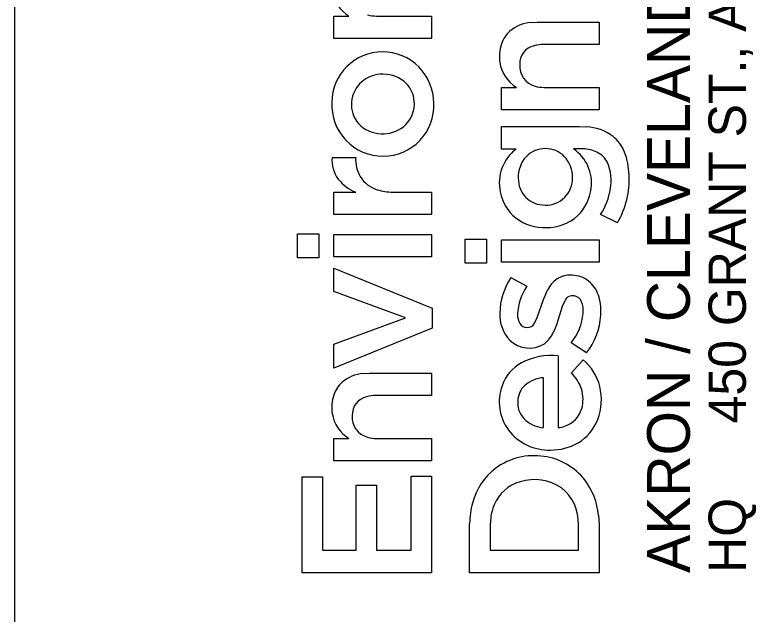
# Model space of a CAD drawing. Extents: x 0 to 54.8, y 0 to 22.
# Drawn here: x 32 to 32.989, y 2.583 to 3.382 of the extents above; entities that cross this region are included whole.
import ezdxf

# ---------------------------------------------------------------- set-up
doc = ezdxf.new("R2010")
doc.units = 0
doc.layers.add('GM_X_Minor_Lake', color=7, linetype='Continuous')
doc.layers.add('GM_X_Township', color=7, linetype='Continuous')

msp = doc.modelspace()

# ---------------------------------------------------------------- linework, layer by layer
at = {"layer": 'GM_X_Minor_Lake'}
for p, q in [((32.42542, 3.38066), (32.44552, 3.38071)), ((32.42542, 3.35086), (32.42542, 3.38066)), ((32.48222, 3.38071), (32.55569, 3.38071)), ((32.55569, 3.38071), (32.55571, 3.35096)), ((32.68784, 3.3722), (32.69634, 3.37266)), ((32.69634, 3.37266), (32.77916, 3.37266)), ((32.77916, 3.37266), (32.77917, 3.34287)), ((32.55571, 3.35096), (32.42542, 3.35086)), ((32.77917, 3.34287), (32.70485, 3.3428)), ((32.64888, 3.2855), (32.66897, 3.28555)), ((32.64888, 3.25569), (32.64888, 3.2855)), ((32.70568, 3.28555), (32.77915, 3.28555)), ((32.77915, 3.28555), (32.77917, 3.25579)), ((32.77917, 3.25579), (32.64888, 3.25569)), ((32.6489, 3.20336), (32.64889, 3.23322)), ((32.64889, 3.23322), (32.75236, 3.23322)), ((32.75236, 3.23322), (32.76191, 3.23285)), ((32.66836, 3.20336), (32.6489, 3.20336)), ((32.75763, 3.20356), (32.74487, 3.20361)), ((32.42299, 3.19193), (32.45454, 3.19193)), ((32.42542, 3.14577), (32.45473, 3.14579)), ((32.42542, 3.11593), (32.42542, 3.14577)), ((32.50413, 3.14581), (32.55571, 3.14573)), ((32.55571, 3.14573), (32.55565, 3.11593)), ((32.55565, 3.11593), (32.42542, 3.11593)), ((32.8036, 3.10491), (32.7812, 3.11598)), ((32.37705, 3.05818), (32.37705, 3.09026)), ((32.37705, 3.09026), (32.40543, 3.09026)), ((32.40543, 3.09026), (32.40543, 3.05818)), ((32.42542, 3.05942), (32.42542, 3.08928)), ((32.42542, 3.08928), (32.55571, 3.08928)), ((32.55571, 3.08928), (32.55571, 3.05942)), ((32.60051, 3.05111), (32.60051, 3.08319)), ((32.60051, 3.08319), (32.62889, 3.08319)), ((32.62889, 3.08319), (32.62889, 3.05111)), ((32.64888, 3.05234), (32.64888, 3.0822)), ((32.64888, 3.0822), (32.77917, 3.0822)), ((32.77917, 3.0822), (32.77917, 3.05234)), ((32.40543, 3.05818), (32.37705, 3.05818)), ((32.55571, 3.05942), (32.42542, 3.05942)), ((32.62889, 3.05111), (32.60051, 3.05111)), ((32.77917, 3.05234), (32.64888, 3.05234)), ((32.42542, 3.01327), (32.42542, 3.0446)), ((32.42542, 3.0446), (32.5567, 2.9913)), ((32.66151, 3.03207), (32.68268, 3.02025)), ((32.70483, 3.00258), (32.71036, 3.01526)), ((32.52117, 2.97798), (32.42542, 3.01327)), ((32.69675, 2.97868), (32.70483, 3.00258)), ((32.73342, 3.00101), (32.72985, 2.9933)), ((32.5567, 2.9913), (32.5567, 2.96441)), ((32.72985, 2.9933), (32.72213, 2.96882)), ((32.42542, 2.94294), (32.52117, 2.97798)), ((32.69299, 2.97117), (32.69675, 2.97868)), ((32.72213, 2.96882), (32.71822, 2.95921)), ((32.5567, 2.96441), (32.42542, 2.91086)), ((32.42542, 2.91086), (32.42542, 2.94294)), ((32.76214, 2.93141), (32.74198, 2.94469)), ((32.72453, 2.92747), (32.72463, 2.83195)), ((32.74228, 2.90465), (32.75768, 2.922)), ((32.46439, 2.90397), (32.47289, 2.90443)), ((32.47289, 2.90443), (32.55571, 2.90443)), ((32.55571, 2.90443), (32.55571, 2.87465)), ((32.70489, 2.83182), (32.70489, 2.89834)), ((32.55571, 2.87465), (32.4814, 2.87457)), ((32.70361, 2.83165), (32.70489, 2.83182)), ((32.42542, 2.81728), (32.44552, 2.81733)), ((32.42542, 2.78747), (32.42542, 2.81728)), ((32.48222, 2.81733), (32.55569, 2.81733)), ((32.55569, 2.81733), (32.55571, 2.78756)), ((32.55571, 2.78756), (32.42542, 2.78747)), ((32.38298, 2.63791), (32.38298, 2.76598)), ((32.38298, 2.76598), (32.41012, 2.76598)), ((32.41012, 2.76598), (32.41012, 2.66827)), ((32.52857, 2.66827), (32.52857, 2.76722)), ((32.52857, 2.76722), (32.55571, 2.76722)), ((32.55571, 2.76722), (32.55571, 2.63791)), ((32.45503, 2.66827), (32.45503, 2.75488)), ((32.45503, 2.75488), (32.48218, 2.75488)), ((32.48218, 2.75488), (32.48218, 2.66827)), ((32.63465, 2.71178), (32.63407, 2.7023)), ((32.77847, 2.71497), (32.77917, 2.7021)), ((32.60643, 2.63799), (32.60644, 2.704)), ((32.63407, 2.7023), (32.63407, 2.66838)), ((32.75149, 2.66834), (32.75153, 2.70239)), ((32.77917, 2.7021), (32.77917, 2.638)), ((32.41012, 2.66827), (32.45503, 2.66827)), ((32.48218, 2.66827), (32.52857, 2.66827)), ((32.63407, 2.66838), (32.75149, 2.66834)), ((32.55571, 2.63791), (32.38298, 2.63791)), ((32.77917, 2.638), (32.60643, 2.63799))]:
    msp.add_line(p, q, dxfattribs=at)
for points in [[(32.42542, 3.35086), (32.42542, 3.38066), (32.44552, 3.38071)], [(32.48222, 3.38071), (32.55569, 3.38071), (32.55571, 3.35096), (32.42542, 3.35086)], [(32.68784, 3.3722), (32.69634, 3.37266), (32.77916, 3.37266), (32.77917, 3.34287), (32.70485, 3.3428)], [(32.64888, 3.25569), (32.64888, 3.2855), (32.66897, 3.28555)], [(32.70568, 3.28555), (32.77915, 3.28555), (32.77917, 3.25579), (32.64888, 3.25569)], [(32.66836, 3.20336), (32.6489, 3.20336), (32.64889, 3.23322), (32.75236, 3.23322), (32.76191, 3.23285)], [(32.75763, 3.20356), (32.74487, 3.20361)], [(32.42299, 3.19193), (32.45454, 3.19193)], [(32.50413, 3.14581), (32.55571, 3.14573), (32.55565, 3.11593), (32.42542, 3.11593)], [(32.42542, 3.11593), (32.42542, 3.14577), (32.45473, 3.14579)], [(32.8036, 3.10491), (32.7812, 3.11598)], [(32.66151, 3.03207), (32.68268, 3.02025)], [(32.69299, 2.97117), (32.69675, 2.97868), (32.70483, 3.00258), (32.71036, 3.01526)], [(32.73342, 3.00101), (32.72985, 2.9933), (32.72213, 2.96882), (32.71822, 2.95921)], [(32.76214, 2.93141), (32.74198, 2.94469)], [(32.72453, 2.92747), (32.72463, 2.83195)], [(32.74228, 2.90465), (32.75768, 2.922)], [(32.46439, 2.90397), (32.47289, 2.90443), (32.55571, 2.90443), (32.55571, 2.87465), (32.4814, 2.87457)], [(32.70361, 2.83165), (32.70489, 2.83182), (32.70489, 2.89834)], [(32.42542, 2.78747), (32.42542, 2.81728), (32.44552, 2.81733)], [(32.48222, 2.81733), (32.55569, 2.81733), (32.55571, 2.78756), (32.42542, 2.78747)], [(32.77847, 2.71497), (32.77917, 2.7021), (32.77917, 2.638), (32.60643, 2.63799)], [(32.63465, 2.71178), (32.63407, 2.7023), (32.63407, 2.66838), (32.75149, 2.66834), (32.75153, 2.70239)], [(32.60643, 2.63799), (32.60644, 2.704)]]:
    msp.add_lwpolyline(points, dxfattribs=at)
for points in [[(32.37705, 3.05818), (32.37705, 3.09026), (32.40543, 3.09026), (32.40543, 3.05818)], [(32.42542, 3.05942), (32.42542, 3.08928), (32.55571, 3.08928), (32.55571, 3.05942)], [(32.60051, 3.05111), (32.60051, 3.08319), (32.62889, 3.08319), (32.62889, 3.05111)], [(32.64888, 3.05234), (32.64888, 3.0822), (32.77917, 3.0822), (32.77917, 3.05234)], [(32.42542, 2.91086), (32.42542, 2.94294), (32.52117, 2.97798), (32.42542, 3.01327), (32.42542, 3.0446), (32.5567, 2.9913), (32.5567, 2.96441)], [(32.38298, 2.63791), (32.38298, 2.76598), (32.41012, 2.76598), (32.41012, 2.66827), (32.45503, 2.66827), (32.45503, 2.75488), (32.48218, 2.75488), (32.48218, 2.66827), (32.52857, 2.66827), (32.52857, 2.76722), (32.55571, 2.76722), (32.55571, 2.63791)]]:
    msp.add_lwpolyline(points, close=True, dxfattribs=at)
for centre, radius, start, end in [((32.47027, 3.42141), 0.04763, 188.96462, 238.69865), ((32.47027, 3.42141), 0.04763, 188.96462, 238.69865), ((32.48183, 3.42286), 0.04215, 254.08913, 270.52838), ((32.48183, 3.42286), 0.04215, 254.08913, 270.52838), ((32.69216, 3.32251), 0.04988, 94.97056, 130.22484), ((32.69216, 3.32251), 0.04988, 94.97056, 130.22484), ((32.68694, 3.33085), 0.04016, 132.22383, 161.68229), ((32.68694, 3.33085), 0.04016, 132.22383, 161.68229), ((32.70217, 3.32642), 0.05602, 162.27398, 187.79173), ((32.70217, 3.32642), 0.05602, 162.27398, 187.79173), ((32.70453, 3.29679), 0.04601, 89.60515, 105.33026), ((32.70453, 3.29679), 0.04601, 89.60515, 105.33026), ((32.49014, 3.26543), 0.0674, 89.84756, 179.64047), ((32.49014, 3.26543), 0.0674, 89.84756, 179.64047), ((32.49057, 3.26474), 0.0681, 359.54009, 90.21138), ((32.49057, 3.26474), 0.0681, 359.54009, 90.21138), ((32.69828, 3.31689), 0.02498, 103.68683, 182.21395), ((32.69828, 3.31689), 0.02498, 103.68683, 182.21395), ((32.69372, 3.32624), 0.04763, 188.96462, 238.69865), ((32.69372, 3.32624), 0.04763, 188.96462, 238.69865), ((32.7008, 3.31381), 0.02757, 175.58441, 255.13816), ((32.7008, 3.31381), 0.02757, 175.58441, 255.13816), ((32.48923, 3.26263), 0.0404, 87.04809, 175.57259), ((32.48923, 3.26263), 0.0404, 87.04809, 175.57259), ((32.49204, 3.25999), 0.04299, 45.84264, 90.98008), ((32.49204, 3.25999), 0.04299, 45.84264, 90.98008), ((32.49458, 3.26421), 0.03821, 357.88569, 44.15902), ((32.49458, 3.26421), 0.03821, 357.88569, 44.15902), ((32.70529, 3.32769), 0.04215, 254.08913, 270.52838), ((32.70529, 3.32769), 0.04215, 254.08913, 270.52838), ((32.49083, 3.26209), 0.06819, 176.8344, 270.40384), ((32.49083, 3.26209), 0.06819, 176.8344, 270.40384), ((32.48729, 3.2625), 0.03848, 175.15378, 221.14706), ((32.48729, 3.2625), 0.03848, 175.15378, 221.14706), ((32.49123, 3.26139), 0.06749, 270.06243, 2.37759), ((32.49123, 3.26139), 0.06749, 270.06243, 2.37759), ((32.49446, 3.26318), 0.0383, 308.28936, 359.43468), ((32.49446, 3.26318), 0.0383, 308.28936, 359.43468), ((32.48919, 3.26607), 0.04228, 223.09994, 268.80895), ((32.48919, 3.26607), 0.04228, 223.09994, 268.80895), ((32.49096, 3.2679), 0.04418, 266.56515, 308.06078), ((32.49096, 3.2679), 0.04418, 266.56515, 308.06078), ((32.75907, 3.16789), 0.06503, 53.40344, 87.49062), ((32.75907, 3.16789), 0.06503, 53.40344, 87.49062), ((32.76517, 3.18039), 0.05141, 21.60748, 50.5577), ((32.76517, 3.18039), 0.05141, 21.60748, 50.5577), ((32.70292, 3.15813), 0.05692, 127.37482, 192.22468), ((32.70292, 3.15813), 0.05692, 127.37482, 192.22468), ((32.70693, 3.16927), 0.0346, 88.47302, 136.42562), ((32.70693, 3.16927), 0.0346, 88.47302, 136.42562), ((32.70814, 3.16963), 0.03424, 44.27195, 90.47623), ((32.70814, 3.16963), 0.03424, 44.27195, 90.47623), ((32.71421, 3.15829), 0.05472, 352.1125, 55.92295), ((32.71421, 3.15829), 0.05472, 352.1125, 55.92295), ((32.75666, 3.15725), 0.04633, 65.01687, 88.8011), ((32.75666, 3.15725), 0.04633, 65.01687, 88.8011), ((32.71141, 3.16602), 0.0401, 137.46739, 182.33237), ((32.71141, 3.16602), 0.0401, 137.46739, 182.33237), ((32.70368, 3.166), 0.03996, 358.57141, 43.53765), ((32.70368, 3.166), 0.03996, 358.57141, 43.53765), ((32.7626, 3.17155), 0.03085, 26.26808, 63.80301), ((32.7626, 3.17155), 0.03085, 26.26808, 63.80301), ((32.73069, 3.16714), 0.08835, 1.15143, 21.3627), ((32.73069, 3.16714), 0.08835, 1.15143, 21.3627), ((32.46616, 3.18882), 0.04329, 175.87313, 216.34747), ((32.46616, 3.18882), 0.04329, 175.87313, 216.34747), ((32.50087, 3.18948), 0.04639, 176.9688, 209.60636), ((32.50087, 3.18948), 0.04639, 176.9688, 209.60636), ((32.73565, 3.16154), 0.05953, 349.30734, 23.43071), ((32.73565, 3.16154), 0.05953, 349.30734, 23.43071), ((32.49514, 3.18814), 0.04079, 211.94466, 253.2028), ((32.49514, 3.18814), 0.04079, 211.94466, 253.2028), ((32.70645, 3.1637), 0.03511, 178.88208, 271.08374), ((32.70645, 3.1637), 0.03511, 178.88208, 271.08374), ((32.70818, 3.16404), 0.03546, 268.27882, 1.55016), ((32.70818, 3.16404), 0.03546, 268.27882, 1.55016), ((32.70538, 3.16244), 0.11383, 329.6388, 3.25998), ((32.70538, 3.16244), 0.11383, 329.6388, 3.25998), ((32.47466, 3.19716), 0.05511, 218.09809, 248.7907), ((32.47466, 3.19716), 0.05511, 218.09809, 248.7907), ((32.50465, 3.2165), 0.07069, 252.46555, 269.57296), ((32.50465, 3.2165), 0.07069, 252.46555, 269.57296), ((32.70463, 3.15696), 0.05837, 190.75182, 231.28919), ((32.70463, 3.15696), 0.05837, 190.75182, 231.28919), ((32.70988, 3.15708), 0.05887, 313.74196, 353.8554), ((32.70988, 3.15708), 0.05887, 313.74196, 353.8554), ((32.70738, 3.16334), 0.08771, 327.31495, 351.57478), ((32.70738, 3.16334), 0.08771, 327.31495, 351.57478), ((32.70954, 3.15901), 0.06051, 269.6361, 312.70877), ((32.70954, 3.15901), 0.06051, 269.6361, 312.70877), ((32.70632, 3.16112), 0.06269, 232.46061, 272.59022), ((32.70632, 3.16112), 0.06269, 232.46061, 272.59022), ((32.7406, 3.0026), 0.03263, 80.17192, 122.51969), ((32.7406, 3.0026), 0.03263, 80.17192, 122.51969), ((32.73636, 2.98258), 0.08973, 146.53104, 178.7571), ((32.73636, 2.98258), 0.08973, 146.53104, 178.7571), ((32.74661, 2.99713), 0.04053, 125.51182, 153.41595), ((32.74661, 2.99713), 0.04053, 125.51182, 153.41595), ((32.74278, 2.99824), 0.03667, 47.79344, 84.68918), ((32.74278, 2.99824), 0.03667, 47.79344, 84.68918), ((32.73788, 2.9946), 0.04267, 14.9966, 46.20632), ((32.73788, 2.9946), 0.04267, 14.9966, 46.20632), ((32.74519, 2.9789), 0.07495, 146.51121, 176.91007), ((32.74519, 2.9789), 0.07495, 146.51121, 176.91007), ((32.74384, 2.99631), 0.01143, 76.66094, 155.7053), ((32.74384, 2.99631), 0.01143, 76.66094, 155.7053), ((32.74397, 2.99511), 0.01256, 21.5098, 78.52618), ((32.74397, 2.99511), 0.01256, 21.5098, 78.52618), ((32.71044, 2.98674), 0.07121, 355.83062, 15.39138), ((32.71044, 2.98674), 0.07121, 355.83062, 15.39138), ((32.72592, 2.98766), 0.03209, 354.57264, 22.06805), ((32.72592, 2.98766), 0.03209, 354.57264, 22.06805), ((32.69666, 2.98238), 0.05005, 177.53659, 222.79318), ((32.69666, 2.98238), 0.05005, 177.53659, 222.79318), ((32.6931, 2.98233), 0.02276, 178.47474, 211.08679), ((32.6931, 2.98233), 0.02276, 178.47474, 211.08679), ((32.68248, 2.99149), 0.0757, 321.81101, 354.79685), ((32.68248, 2.99149), 0.0757, 321.81101, 354.79685), ((32.68952, 2.9882), 0.09219, 321.9777, 355.87384), ((32.68952, 2.9882), 0.09219, 321.9777, 355.87384), ((32.68331, 2.9767), 0.01148, 212.23676, 268.37769), ((32.68331, 2.9767), 0.01148, 212.23676, 268.37769), ((32.68342, 2.97589), 0.01067, 267.71603, 333.73375), ((32.68342, 2.97589), 0.01067, 267.71603, 333.73375), ((32.68098, 2.9758), 0.04077, 308.08772, 335.98736), ((32.68098, 2.9758), 0.04077, 308.08772, 335.98736), ((32.68599, 2.97535), 0.0375, 225.98539, 302.47965), ((32.68599, 2.97535), 0.0375, 225.98539, 302.47965), ((32.7152, 2.84414), 0.08384, 83.61499, 118.28755), ((32.7152, 2.84414), 0.08384, 83.61499, 118.28755), ((32.70239, 2.86906), 0.05583, 118.83082, 160.62438), ((32.70239, 2.86906), 0.05583, 118.83082, 160.62438), ((32.71744, 2.87167), 0.06443, 13.53365, 51.36148), ((32.71744, 2.87167), 0.06443, 13.53365, 51.36148), ((32.46871, 2.85428), 0.04988, 94.96958, 130.22249), ((32.46871, 2.85428), 0.04988, 94.96958, 130.22249), ((32.70785, 2.85609), 0.04235, 94.00805, 130.88169), ((32.70785, 2.85609), 0.04235, 94.00805, 130.88169), ((32.70378, 2.86556), 0.05486, 19.03571, 45.44059), ((32.70378, 2.86556), 0.05486, 19.03571, 45.44059), ((32.46348, 2.86263), 0.04015, 132.22192, 161.68183), ((32.46348, 2.86263), 0.04015, 132.22192, 161.68183), ((32.71041, 2.86612), 0.06437, 160.52012, 215.78311), ((32.71041, 2.86612), 0.06437, 160.52012, 215.78311), ((32.70048, 2.86628), 0.02985, 132.98507, 177.179), ((32.70048, 2.86628), 0.02985, 132.98507, 177.179), ((32.70635, 2.86921), 0.07579, 339.3542, 13.37853), ((32.70635, 2.86921), 0.07579, 339.3542, 13.37853), ((32.71069, 2.8697), 0.047, 344.60586, 17.007), ((32.71069, 2.8697), 0.047, 344.60586, 17.007), ((32.47872, 2.85819), 0.05601, 162.27355, 187.79185), ((32.47872, 2.85819), 0.05601, 162.27355, 187.79185), ((32.47482, 2.84867), 0.02498, 103.68646, 182.21874), ((32.47482, 2.84867), 0.02498, 103.68646, 182.21874), ((32.48108, 2.82856), 0.04601, 89.60494, 105.3284), ((32.48108, 2.82856), 0.04601, 89.60494, 105.3284), ((32.7017, 2.86503), 0.03115, 175.00126, 223.28301), ((32.7017, 2.86503), 0.03115, 175.00126, 223.28301), ((32.7224, 2.86715), 0.03504, 288.00773, 343.55078), ((32.7224, 2.86715), 0.03504, 288.00773, 343.55078), ((32.47026, 2.85802), 0.04762, 188.96199, 238.70369), ((32.47026, 2.85802), 0.04762, 188.96199, 238.70369), ((32.47735, 2.84558), 0.02756, 175.58538, 255.14386), ((32.47735, 2.84558), 0.02756, 175.58538, 255.14386), ((32.70891, 2.87363), 0.04231, 225.06188, 262.79738), ((32.70891, 2.87363), 0.04231, 225.06188, 262.79738), ((32.71894, 2.8652), 0.0626, 300.94269, 338.73225), ((32.71894, 2.8652), 0.0626, 300.94269, 338.73225), ((32.71253, 2.87054), 0.06872, 217.74516, 271.65431), ((32.71253, 2.87054), 0.06872, 217.74516, 271.65431), ((32.72474, 2.85216), 0.02021, 269.7003, 294.8711), ((32.72474, 2.85216), 0.02021, 269.7003, 294.8711), ((32.48183, 2.85948), 0.04215, 254.09162, 270.52835), ((32.48183, 2.85948), 0.04215, 254.09162, 270.52835), ((32.71549, 2.87241), 0.07056, 269.20477, 300.33412), ((32.71549, 2.87241), 0.07056, 269.20477, 300.33412), ((32.69229, 2.70792), 0.08641, 81.19402, 125.99844), ((32.69229, 2.70792), 0.08641, 81.19402, 125.99844), ((32.69458, 2.71132), 0.08272, 37.85208, 82.40204), ((32.69458, 2.71132), 0.08272, 37.85208, 82.40204), ((32.69387, 2.70893), 0.08654, 127.23621, 165.14796), ((32.69387, 2.70893), 0.08654, 127.23621, 165.14796), ((32.68893, 2.70782), 0.05398, 106.18808, 157.38609), ((32.68893, 2.70782), 0.05398, 106.18808, 157.38609), ((32.69279, 2.69862), 0.06389, 55.67272, 107.20935), ((32.69279, 2.69862), 0.06389, 55.67272, 107.20935), ((32.68586, 2.70567), 0.09308, 5.73329, 37.30396), ((32.68586, 2.70567), 0.09308, 5.73329, 37.30396), ((32.69291, 2.70499), 0.05867, 357.46616, 52.26647), ((32.69291, 2.70499), 0.05867, 357.46616, 52.26647), ((32.71426, 2.70281), 0.10783, 164.7861, 179.37039), ((32.71426, 2.70281), 0.10783, 164.7861, 179.37039), ((32.69829, 2.70389), 0.06412, 157.35705, 172.92755), ((32.69829, 2.70389), 0.06412, 157.35705, 172.92755)]:
    msp.add_arc(centre, radius, start, end, dxfattribs=at)
at = {"layer": 'GM_X_Township'}
msp.add_line((32, 0.5), (32, 21.5), dxfattribs=at)

# ---------------------------------------------------------------- texts
at = {"layer": 'GM_X_Minor_Lake'}
for s, height, p in [('450 GRANT ST., AKRON, OH  44311', 0.0498462, (32.97489, 2.83738)), ('AKRON / CLEVELAND / COLUMBUS', 0.056969, (32.90012, 2.638)), ('HQ ', 0.049846, (32.97489, 2.638))]:
    msp.add_text(s, height=height, rotation=90, dxfattribs=at).set_placement(p)

doc.saveas('drawing.dxf')
